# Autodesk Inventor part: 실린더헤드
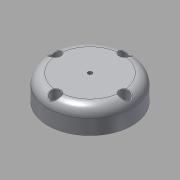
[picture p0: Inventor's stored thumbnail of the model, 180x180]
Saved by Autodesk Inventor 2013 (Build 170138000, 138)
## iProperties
Created: 2016-11
Part Number: 실린더헤드
Material: 알루미늄 6061
Document SubType Name: Modeling
Designer: mduedu
Density: 1 g/cm^3
Author: mduedu
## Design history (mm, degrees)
sketch "스케치1"
  geometry: C1 r 42.5 at (0, 0); 1 further point
  constraints: 1 centre point, 1 coincident
  dimensions: "d0" = 85 diameter of C1
extrude "돌출1" new body sketch "스케치1" distance "d1" = 25; taper "d2" = 0 deg
fillet "모깎기1" dims "d3" = 10
sketch "스케치2"
  geometry: C1 r 30 at (0, 0); 1 further point
  constraints: 1 centre point, 1 coincident
  dimensions: "d4" = 60 diameter of C1
extrude "돌출2" join sketch "스케치2" distance "d5" = 5; taper "d6" = 0 deg
sketch "스케치3"
  geometry: C1 r 25 at (0, 0); 1 further point
  constraints: 1 centre point, 1 coincident
  dimensions: "d7" = 50 diameter of C1
extrude "돌출3" cut sketch "스케치3" distance "d8" = 20; taper "d9" = 0 deg
hole "구멍1" diameter "d12" = 4.134; stored, may be unused: countersink angle "d16" = 90 deg, drill point angle "d18" = 118 deg; dims "d10" = 10, "d11" = 10, "d13" = 6, "d14" = 4, "d15" = 2, "d17" = 8
chamfer "모따기1" distance "d19" = 1; stored, may be unused: second distance "d20" = 2, angle "d21" = 45 deg
fillet "모깎기2" dims "d22" = 3
sketch "스케치4"
  geometry: C1 r 17.5 at (0, 0); 1 further point
  constraints: 1 centre point, 1 coincident
  dimensions: "d23" = 35 diameter of C1
extrude "돌출4" cut sketch "스케치4" distance "d24" = 2; taper "d25" = 0 deg
fillet "모깎기3" dims "d26" = 0.5
sketch "스케치5" dims "d32" = 70
  geometry: C1 r 5 at (0, 35); 3 further points
  constraints: 2 coincident, 2 vertical alignment, 1 centre point, 2 other
  dimensions: "d33" = 10 diameter of C1
extrude "돌출5" cut sketch "스케치5" distance "d34" = 10; taper "d35" = 0 deg
sketch "스케치6" dims "d39" = 70
  geometry: 6 further points
  constraints: 2 vertical alignment, 1 coincident, 7 other
  dimensions: "d42" = 360 deg dimension on point (0, -35) point (0, 0) (derived)
sketch "스케치7"
  geometry: 4 further points
  constraints: 4 other
hole "구멍2" sketch "스케치7" at (0, 70), (-35, 35), (35, 35), (0, 0) diameter "d44" = 5.5; stored, may be unused: countersink angle "d48" = 90 deg, drill point angle "d50" = 0 deg; dims "d45" = 6, "d46" = 4, "d47" = 2, "d49" = 8
fillet "모깎기4" dims "d51" = 0.5
node "솔리드1"
pattern_circular "원형 패턴1" dims angle "d37" = 360 deg
